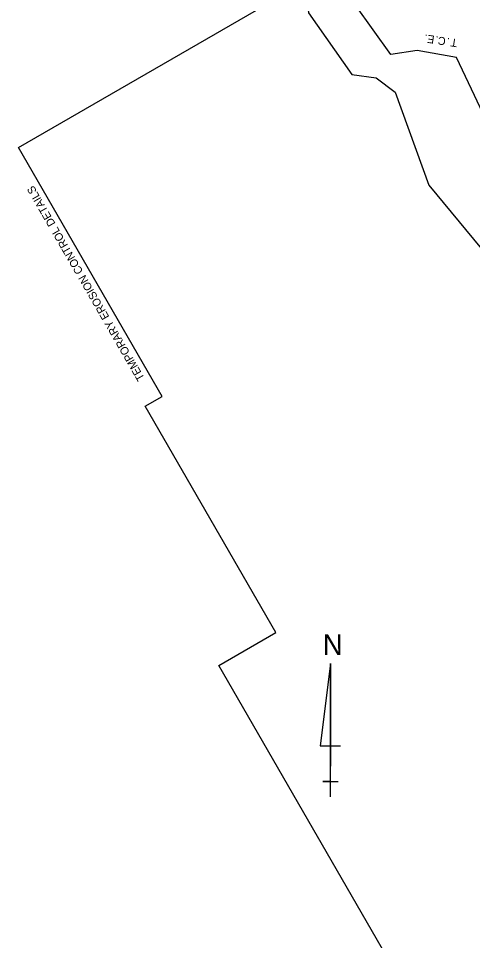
# Model space of a CAD drawing. Extents: x 956270 to 957915, y 1920520 to 1922423.
# Drawn here: x 956270 to 956611, y 1921340 to 1922031 of the extents above; entities that cross this region are included whole.
import ezdxf

# ---------------------------------------------------------------- set-up
doc = ezdxf.new("R2010")
doc.units = 0
for name, color, linetype in [('1', 7, 'Continuous'), ('63', 7, 'Continuous'), ('NO PLOT', 7, 'Continuous'), ('R_Draft', 7, 'Continuous')]:
    doc.layers.add(name, color=color, linetype=linetype)

msp = doc.modelspace()

# ---------------------------------------------------------------- linework, layer by layer
at = {"layer": '63'}
for p, q in [((956504.2, 1921547.25), (956496.5, 1921485.71)), ((956504.2, 1921447.25), (956504.2, 1921547.25)), ((956504.2, 1921547.25), (956504.2, 1921470.33)), ((956496.5, 1921485.71), (956511.89, 1921485.71)), ((956504.2, 1921447.25), (956504.2, 1921470.33)), ((956504.2, 1921458.79), (956498.43, 1921458.79)), ((956498.43, 1921458.79), (956509.97, 1921458.79)), ((956504.2, 1921447.25), (956504.2, 1921458.79))]:
    msp.add_line(p, q, dxfattribs=at)
at = {"layer": 'NO PLOT'}
msp.add_lwpolyline([(957012.51, 1920520.44), (956420.48, 1921545.87), (956463.26, 1921570.57), (956365.36, 1921740.14), (956378, 1921747.44), (956270.25, 1921934.07), (956666.17, 1922162.65), (956816.66, 1921901.98), (956749.98, 1921863.48), (956962.48, 1921495.42), (957029.16, 1921533.92), (957172.25, 1921286.08), (957120.9, 1921256.43), (957292.23, 1920959.68), (957343.58, 1920989.33), (957463.85, 1920781.02)], close=True, dxfattribs=at)
msp.add_lwpolyline([(957012.51, 1920520.44), (956420.48, 1921545.87), (956463.26, 1921570.57), (956365.36, 1921740.14), (956378, 1921747.44), (956270.25, 1921934.07), (956666.17, 1922162.65), (956816.66, 1921901.98), (956749.98, 1921863.48), (956962.48, 1921495.42), (957029.16, 1921533.92), (957172.25, 1921286.08), (957120.9, 1921256.43), (957292.23, 1920959.68), (957343.58, 1920989.33), (957463.85, 1920781.02)], close=True, dxfattribs=at)
msp.add_lwpolyline([(957012.51, 1920520.44), (956420.48, 1921545.87), (956463.26, 1921570.57), (956365.36, 1921740.14), (956378, 1921747.44), (956270.25, 1921934.07), (956666.17, 1922162.65), (956816.66, 1921901.98), (956749.98, 1921863.48), (956962.48, 1921495.42), (957029.16, 1921533.92), (957172.25, 1921286.08), (957120.9, 1921256.43), (957292.23, 1920959.68), (957343.58, 1920989.33), (957463.85, 1920781.02)], close=True, dxfattribs=at)
msp.add_lwpolyline([(956978.43, 1921300.96), (956891.96, 1921416.34), (956761.21, 1921624.84), (956685.68, 1921817.75), (956598.64, 1922001.42), (956569.16, 1922006.84), (956549.42, 1922003.64), (956496.56, 1922078), (956484.6, 1922065.05), (956487.74, 1922034.93), (956520.15, 1921988.76), (956538.43, 1921986.13), (956552.84, 1921975.42), (956577.89, 1921905.71), (956667.63, 1921797.4), (956675.52, 1921785.98), (956734.33, 1921642.98), (956883.87, 1921386.21), (956963.43, 1921282.81)], dxfattribs=at)

# ---------------------------------------------------------------- texts
at = {"layer": '1'}
msp.add_text('TEMPORARY EROSION CONTROL DETAILS', height=6, rotation=120, dxfattribs=at).set_placement((956365.12, 1921761.15))
at = {"layer": '63'}
msp.add_text('N', height=15.38, rotation=360, dxfattribs=at).set_placement((956498.56, 1921553.66))
at = {"layer": 'R_Draft'}
for s, p in [('.', (956577.24, 1922018.5)), ('E', (956582.56, 1922017.69)), ('.', (956585.46, 1922017.25)), ('C', (956591.06, 1922016.4)), ('.', (956593.96, 1922015.97)), ('T', (956599.75, 1922015.09))]:
    msp.add_text(s, height=6, rotation=171.38948, dxfattribs=at).set_placement(p)

doc.saveas('drawing.dxf')
